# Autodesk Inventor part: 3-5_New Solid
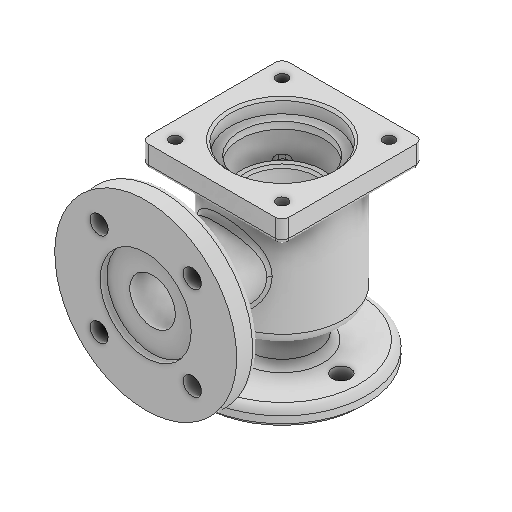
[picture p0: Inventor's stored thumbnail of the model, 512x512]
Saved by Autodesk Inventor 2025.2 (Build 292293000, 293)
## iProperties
Created: 2025-01
Part Number: 3-5_New Solid
Material: Generic
Document SubType Name: Modeling
Designer: Dennis
Density: 1 g/cm^3
Appearance: Default
Mass: 197.886 g
Surface Area: 696.426 cm^2
Volume: 197.886 cm^3
Author: Dennis
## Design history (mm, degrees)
sketch "Sketch1"
  geometry: L1 (0, 0)-(0, -37); L2 (0, -37)-(5, -37); L3 (8, -34)-(8, -18); L4 (11, -15)-(20, -15); L5 (24, -19)-(24, -22); L6 (29, -27)-(74, -27); L7 (74, -27)-(74, 0); L8 (74, 0)-(0, 0); A1 r 3 centre (5, -34) between (5, -37) and (8, -34); A2 r 3 centre (11, -18) between (11, -15) and (8, -18); A3 r 4 centre (20, -19) between (24, -19) and (20, -15); A4 r 5 centre (29, -22) between (24, -22) and (29, -27)
  constraints: 16 end point, 8 point on circle, 8 tangent, 7 perpendicular, 4 centre point, 1 equal radius, 1 vertical
  dimensions: "d0" = 74 diameter of L2 L8; "d1" = 30 diameter of L4 L8; "d2" = 54 diameter of L6 L8; "d3" = 8 distance between parallel lines of L1 L3; "d4" = 16 distance between parallel lines of L3 L5; "d5" = 74 distance between parallel lines of L1 L7; "d6" = 3 radius of A1 (derived); "d7" = 4 radius of A3; "d8" = 5 radius of A4
revolve "Revolution1" sketch "Sketch1" stored, may be unused: angle "d9" = 90 deg
sketch "Sketch2"
  geometry: L1 (0, 72)-(0, -12) reference; L2 (-10.2, 0)-(61.2, 0) reference; L3 (51, 60)-(51, 0); L4 (51, 60)-(11, 60); L5 (11, 60)-(11, 53); L6 (14, 50)-(31, 50); L7 (35, 46)-(35, 0); L8 (35, 0)-(51, 0); A1 r 4 centre (31, 46) between (35, 46) and (31, 50); A2 r 3 centre (14, 53) between (11, 53) and (14, 50); 1 further point
  constraints: 12 end point, 4 point on circle, 4 tangent, 3 perpendicular, 2 centre point, 2 horizontal, 2 point on line, 1 parallel
  dimensions: "d10" = 51 distance between parallel lines of L1 L3; "d11" = 32 diameter of L7 L3; "d12" = 80 diameter of L5 L3; "d13" = 10 distance between parallel lines of L6 L4; "d14" = 60 distance between parallel lines of L2 L4; "d15" = 4 radius of A1; "d16" = 3 radius of A2
revolve "Revolution2" sketch "Sketch2" stored, may be unused: angle "d17" = 90 deg
sketch "Sketch3"
  geometry: L1 (28, 31)-(-28, 31); L2 (-31, 28)-(-31, -28); L3 (-28, -31)-(28, -31); L4 (31, -28)-(31, 28); L5 (31, 31)-(-31, -31); L6 (-31, 31)-(31, -31); A1 r 3 centre (-28, -28) between (-31, -28) and (-28, -31); A2 r 3 centre (28, -28) between (28, -31) and (31, -28); A3 r 3 centre (28, 28) between (31, 28) and (28, 31); A4 r 3 centre (-28, 28) between (-28, 31) and (-31, 28); 1 further point
  constraints: 12 end point, 8 point on circle, 8 point on line, 8 tangent, 4 centre point, 3 equal radius, 2 midpoint, 2 parallel, 2 perpendicular, 1 horizontal
  dimensions: "d18" = 62 distance between parallel lines of L1 L3; "d19" = 3 radius of A1
extrude "Extrusion1" join sketch "Sketch3" distance "d20" = 10; taper "d21" = 0 deg
fillet "Fillet1" dims "d22" = 2
sketch "Sketch4"
  geometry: L1 (-18.2, 0)-(109.2, 0) reference; L2 (84, -28)-(84, 28) reference; L3 (0, 37)-(0, -37) reference; L4 (84, -22.5)-(78, -22.5); L5 (78, -22.5)-(78, -18.5); L6 (78, -18.5)-(75, -18.5); L7 (75, -18.5)-(75, -20.5); L8 (73, -22.5)-(30, -22.5); L9 (28, -20.5)-(28, -10); L10 (28, -10)-(3, -10); L11 (3, -10)-(3, -16); L12 (3, -16)-(0, -16); L13 (0, -16)-(0, 0); L14 (84, 0)-(84, -22.5); A1 r 2 centre (30, -20.5) between (28, -20.5) and (30, -22.5); A2 r 2 centre (73, -20.5) between (73, -22.5) and (75, -20.5); 1 further point
  constraints: 22 end point, 7 perpendicular, 4 point on circle, 4 tangent, 2 centre point, 2 collinear, 2 point on line, 2 vertical, 1 equal radius, 1 horizontal, 1 midpoint
  dimensions: "d23" = 20 diameter of L10 L1; "d24" = 32 diameter of L12 L1; "d25" = 45 diameter of L4 L1; "d26" = 37 diameter of L6 L1; "d27" = 3 distance between parallel lines of L7 L5; "d29" = 28 distance between parallel lines of L3 L9; "d30" = 3 distance between parallel lines of L3 L11; "d31" = 6 distance between parallel lines of L5 L2; "d32" = 2 radius of A1
revolve "Revolution3" sketch "Sketch4" stored, may be unused: angle "d33" = 90 deg
sketch "Sketch5"
  geometry: L1 (11, 60)-(91, 60) reference; L2 (51, 60)-(51, 4.677); L3 (51, 4.677)-(61, 4.677); L4 (61, 4.677)-(61, 57); L5 (61, 57)-(71, 57); L6 (71, 57)-(71, 60); L7 (71, 60)-(51, 60); 1 further point
  constraints: 12 end point, 4 perpendicular, 1 collinear, 1 midpoint, 1 point on line, 1 vertical
  dimensions: "d34" = 40 diameter of L6 L2; "d35" = 20 diameter of L4 L2; "d36" = 3 distance between parallel lines of L1 L5
revolve "Revolution4" sketch "Sketch5" stored, may be unused: angle "d37" = 90 deg
sketch "Sketch6"
  geometry: L1 (-18.2, 0)-(109.2, 0) reference; L2 (38.5, 0)-(38.5, -18); L3 (38.5, -18)-(63.5, -18); L4 (63.5, -18)-(63.5, 0); L5 (51, 60)-(51, 0) reference; 2 further points
  constraints: 6 end point, 1 parallel, 1 point on line, 1 other
  dimensions: "d38" = 25 distance between parallel lines of L2 L4; "d39" = 36 diameter of L3 L1
revolve "Revolution5" sketch "Sketch6" stored, may be unused: angle "d40" = 90 deg
workplane "Work Plane1"
sketch "Sketch7"
  geometry: L1 (73, -22.5)-(30, -22.5) reference; L2 (-18.2, 0)-(109.2, 0) reference; L3 (61.5, 0)-(40.5, 0); L4 (40.5, 0)-(40.5, -22.5); L5 (40.5, -22.5)-(61.5, -22.5); L6 (61.5, -22.5)-(61.5, 0); L7 (63.5, -18)-(63.5, 18) reference; L8 (38.5, -18)-(38.5, 18) reference; 1 further point
  constraints: 8 end point, 2 parallel, 2 point on line, 1 horizontal, 1 perpendicular
  dimensions: "d42" = 2 distance between parallel lines of L7 L6; "d43" = 2 distance between parallel lines of L8 L4 (= d42)
extrude "Extrusion2" join sketch "Sketch7" stored distance "d44" = 4; taper "d45" = 0 deg
fillet "Fillet2" dims "d46" = 1
pattern_circular "Circular Pattern1" dims "d49" = 360 deg
fillet "Fillet3" dims "d47" = 1
sketch "Sketch8"
  geometry: L1 (63.5, -18)-(63.5, 18) reference; L2 (38.5, -18)-(38.5, 18) reference; L3 (-18.2, 0)-(109.2, 0) reference; L4 (38.5, 0)-(38.5, -15); L5 (38.5, -15)-(63.5, -15); L6 (63.5, -15)-(63.5, 0); 1 further point
  constraints: 6 end point, 4 point on line, 2 midpoint, 1 perpendicular
  dimensions: "d51" = 30 diameter of L5 L3
revolve "Revolution6" sketch "Sketch8" stored, may be unused: angle "d52" = 90 deg
chamfer "Chamfer1" distance "d53" = 1; stored, may be unused: second distance "d54" = 2, angle "d55" = 45 deg
sketch "Sketch9"
  geometry: L1 (23.5, -23.5)-(-23.5, -23.5); L2 (-23.5, -23.5)-(-23.5, 23.5); L3 (-23.5, 23.5)-(23.5, 23.5); L4 (23.5, 23.5)-(23.5, -23.5); L5 (23.5, -23.5)-(-23.5, 23.5); L6 (-23.5, -23.5)-(23.5, 23.5); 5 further points
  constraints: 12 end point, 4 coincident, 2 midpoint, 2 parallel, 2 perpendicular, 1 horizontal
  dimensions: "d56" = 47 distance of L1.end L2.end
hole "Hole1" sketch "Sketch9" at (-23.5, 23.5), (23.5, -23.5), (23.5, 23.5), (-23.5, -23.5) diameter "d57" = 4.917; stored, may be unused: countersink angle "d61" = 90 deg, drill point angle "d63" = 118 deg; dims "d58" = 12, "d59" = 4, "d60" = 2, "d62" = 8
sketch "Sketch10" dims "d64" = 52
  geometry: L1 (0, 0)-(0, -26); 5 further points
  constraints: 2 coincident, 2 end point, 1 vertical, 1 vertical alignment, 7 other
  dimensions: "d67" = 360 deg dimension on L1.start point (0, -26) (derived)
hole "Hole2" sketch "Sketch10" at (0, -26), (26, 0), (0, 26), (-26, 0) diameter "d69" = 8; stored, may be unused: countersink angle "d73" = 90 deg, drill point angle "d75" = 118 deg; dims "d70" = 12, "d71" = 4, "d72" = 2, "d74" = 8
sketch "Sketch11" dims "d76" = 58
  geometry: L1 (0, 58.2)-(0, -69.2) reference; L2 (0, 0)-(20.506, 20.506); C1 r 40 at (0, 0) reference; 5 further points
  constraints: 2 coincident, 2 end point, 8 other
  dimensions: "d77" = 45 deg angle of L1 L2; "d80" = 360 deg dimension on C1.centre point (20.506, 20.506) (derived)
hole "Hole3" sketch "Sketch11" at (20.506, 20.506), (-20.506, 20.506), (-20.506, -20.506), (20.506, -20.506) diameter "d82" = 8; stored, may be unused: countersink angle "d86" = 90 deg, drill point angle "d88" = 118 deg; dims "d83" = 6, "d84" = 4, "d85" = 2, "d87" = 8
chamfer "Chamfer2" distance "d91" = 2; stored, may be unused: second distance "d92" = 2, angle "d93" = 45 deg
body "Solid1"
node "Sketch Circular Pattern1" dims "d67" = 360 deg (derived)
node "Sketch Circular Pattern2" dims "d80" = 360 deg (derived)
other parameters: "d41" = 45 deg
